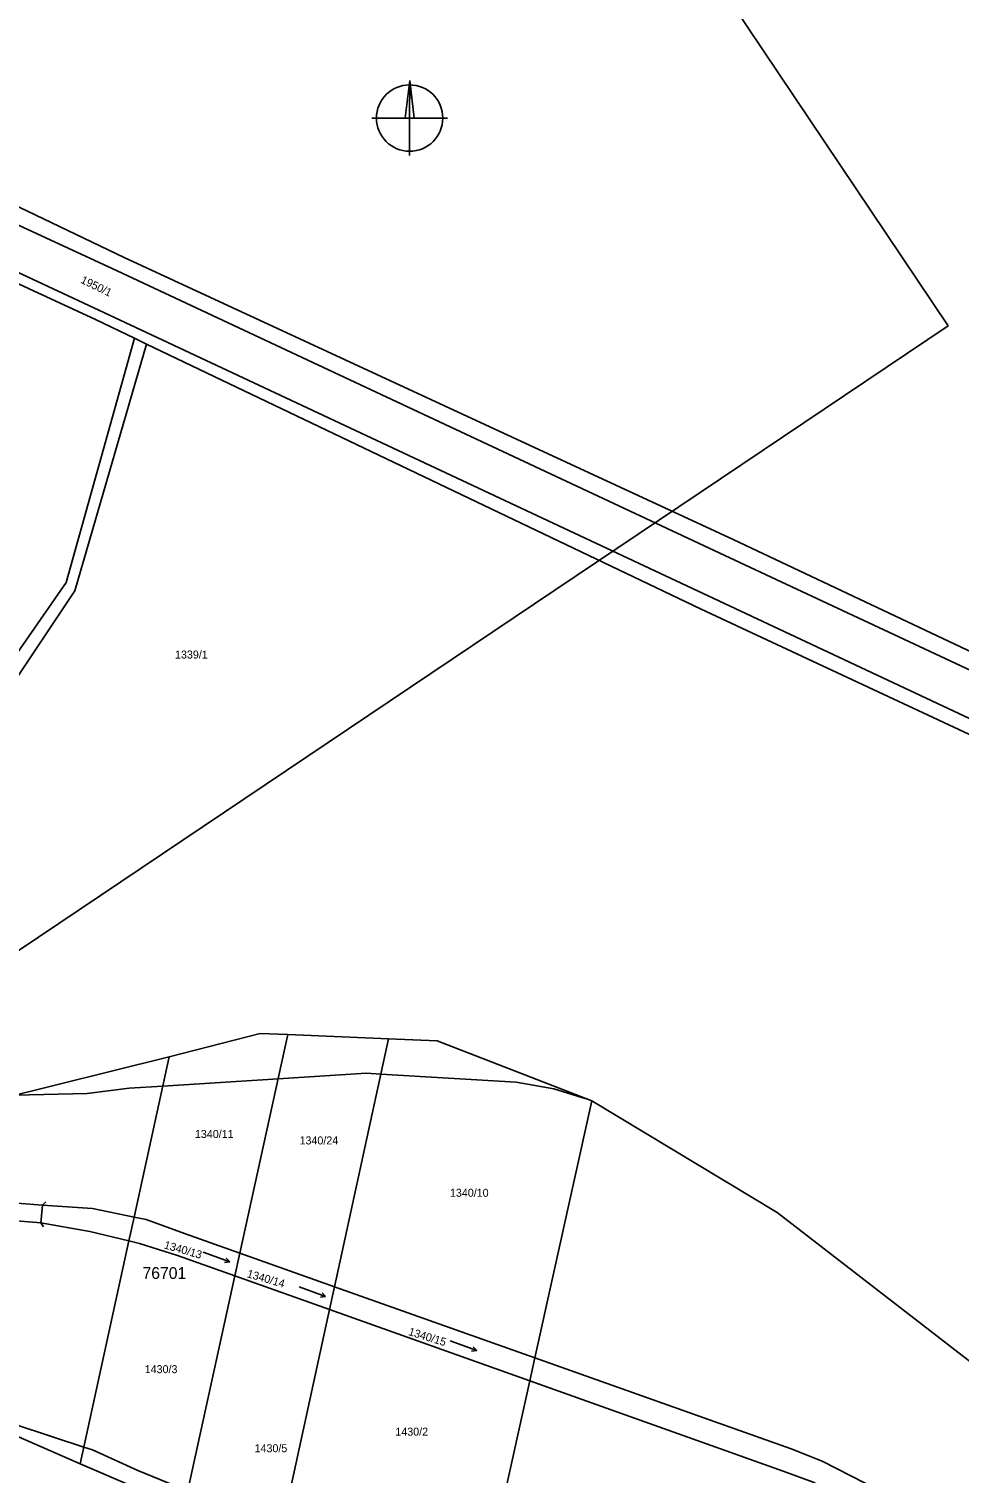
# Model space of a CAD drawing. Extents: x -794765 to -785424, y -1118958 to -1108731.
# Drawn here: x -787203.5 to -787005.8, y -1117691.3 to -1117384.5 of the extents above; entities that cross this region are included whole.
import ezdxf

# ---------------------------------------------------------------- set-up
doc = ezdxf.new("R2010")
doc.units = 0
for name, color, linetype in [('Level 66', 7, 'Continuous'), ('Level 71', 7, 'Continuous'), ('Level 75', 7, 'Continuous'), ('Level 76', 7, 'Continuous'), ('Level 77', 7, 'Continuous'), ('Level 81', 7, 'Continuous')]:
    doc.layers.add(name, color=color, linetype=linetype)

msp = doc.modelspace()

# ---------------------------------------------------------------- linework, layer by layer
at = {"layer": 'Level 66'}
for p, q in [((-787166.44, -1117644.39), (-787160.8, -1117646.44)), ((-787160.8, -1117646.44), (-787161.54, -1117645.64)), ((-787160.8, -1117646.44), (-787161.89, -1117646.58)), ((-787146.08, -1117651.74), (-787140.44, -1117653.79)), ((-787140.44, -1117653.79), (-787141.53, -1117653.93)), ((-787140.44, -1117653.79), (-787141.18, -1117652.99)), ((-787113.97, -1117663.23), (-787108.33, -1117665.28)), ((-787108.33, -1117665.28), (-787109.07, -1117664.48)), ((-787108.33, -1117665.28), (-787109.42, -1117665.42))]:
    msp.add_line(p, q, dxfattribs=at)
at = {"layer": 'Level 71'}
for p, q in [((-787122.56, -1117395.5), (-787123.56, -1117403.43)), ((-787130.64, -1117403.46), (-787114.51, -1117403.5)), ((-787122.59, -1117403.46), (-787122.62, -1117411.43)), ((-787257.85, -1117615.31), (-787008.17, -1117447.61))]:
    msp.add_line(p, q, dxfattribs=at)
msp.add_lwpolyline([(-787008.17, -1117447.61), (-787479.8, -1116745.45), (-787729.47, -1116913.15), (-787257.85, -1117615.31)], dxfattribs=at)
msp.add_lwpolyline([(-787122.56, -1117395.5), (-787121.59, -1117403.46), (-787122.59, -1117403.46)], close=True, dxfattribs=at)
msp.add_circle((-787122.59, -1117403.46), 7.05, dxfattribs=at)
at = {"layer": 'Level 75'}
for p, q in [((-787181.08, -1117450.22), (-787178.49, -1117451.46)), ((-787158.66, -1117644.58), (-787148.45, -1117598.16)), ((-787148.45, -1117598.16), (-787127.04, -1117599.06)), ((-787127.04, -1117599.06), (-787138.55, -1117651.72)), ((-787173.69, -1117602.87), (-787181.14, -1117636.92)), ((-787095.98, -1117666.83), (-787083.89, -1117612.23)), ((-787181.14, -1117636.92), (-787182.24, -1117641.97)), ((-787182.24, -1117641.97), (-787192.6, -1117689.33)), ((-787159.72, -1117649.37), (-787158.66, -1117644.58)), ((-787138.55, -1117651.72), (-787158.66, -1117644.58)), ((-787170.58, -1117698.74), (-787159.72, -1117649.37)), ((-787159.72, -1117649.37), (-787139.61, -1117656.54)), ((-787139.61, -1117656.54), (-787138.55, -1117651.72)), ((-787095.98, -1117666.83), (-787138.55, -1117651.72)), ((-787139.61, -1117656.54), (-787150.69, -1117707.23)), ((-787139.61, -1117656.54), (-787097.06, -1117671.7)), ((-787095.98, -1117666.83), (-787097.06, -1117671.7)), ((-787103.7, -1117701.74), (-787097.06, -1117671.7)), ((-787170.58, -1117698.74), (-787192.6, -1117689.33))]:
    msp.add_line(p, q, dxfattribs=at)
for points in [[(-786706.11, -1117656.27), (-786875.36, -1117577.21), (-787053.8, -1117493.01), (-787183.24, -1117433.1), (-787248.32, -1117401.92)], [(-787181.08, -1117450.22), (-787189.33, -1117446.27), (-787252.97, -1117416.89)], [(-787270.37, -1117609.83), (-787195.54, -1117502.09), (-787181.08, -1117450.22)], [(-787265.2, -1117611.01), (-787193.72, -1117503.85), (-787178.49, -1117451.46)], [(-787178.49, -1117451.46), (-787060.65, -1117507.79), (-786888.93, -1117587.94), (-786715.31, -1117668.78), (-786654.85, -1117697.18), (-786554.23, -1117744.76)], [(-787148.45, -1117598.16), (-787154.33, -1117597.92), (-787173.69, -1117602.87)], [(-787083.89, -1117612.23), (-787116.72, -1117599.48), (-787127.04, -1117599.06)], [(-787265.2, -1117611.01), (-787210.23, -1117611.92), (-787173.69, -1117602.87)], [(-787083.89, -1117612.23), (-787044.5, -1117635.94), (-786988.98, -1117678.85), (-786894.96, -1117721.22), (-786804.51, -1117760.36), (-786783.82, -1117759.58), (-786698.19, -1117799.48), (-786641.23, -1117819.18), (-786564.05, -1117798.26)], [(-787181.14, -1117636.92), (-787190.01, -1117635.11), (-787200.57, -1117634.38), (-787211.61, -1117633.55), (-787292.23, -1117625.71), (-787296.84, -1117625.58)], [(-787296.23, -1117630.19), (-787293.12, -1117630.97), (-787212.29, -1117637.24), (-787200.96, -1117638.15), (-787190.55, -1117639.98), (-787182.24, -1117641.97)], [(-787158.66, -1117644.58), (-787170.42, -1117640.41), (-787178.57, -1117637.44), (-787181.14, -1117636.92)], [(-787182.24, -1117641.97), (-787180.01, -1117642.5), (-787171.88, -1117645.04), (-787159.72, -1117649.37)], [(-787192.6, -1117689.33), (-787260.59, -1117659.56), (-787270.16, -1117662.49), (-787292.35, -1117650.03)], [(-786847.1, -1117813.31), (-786936.77, -1117752.44), (-787017.15, -1117698.96), (-787025.67, -1117693.51), (-787034.95, -1117688.76), (-787041.51, -1117686.17), (-787095.98, -1117666.83)], [(-787097.06, -1117671.7), (-787043.19, -1117690.9), (-787036.8, -1117693.22), (-787027.75, -1117697.82), (-787019.6, -1117702.92), (-786939.62, -1117757.05), (-786798.58, -1117851.66)]]:
    msp.add_lwpolyline(points, dxfattribs=at)
at = {"layer": 'Level 77'}
for p, q in [((-787250.51, -1117405.41), (-787184.71, -1117435.94)), ((-787188.65, -1117444.27), (-787252.33, -1117414.61)), ((-787184.71, -1117435.94), (-787055.59, -1117496.38)), ((-787059.18, -1117504.94), (-787188.65, -1117444.27)), ((-787055.59, -1117496.38), (-786877.84, -1117579.46)), ((-786886.62, -1117585.85), (-787059.18, -1117504.94)), ((-787199.88, -1117633.66), (-787200.57, -1117634.38)), ((-787200.57, -1117634.38), (-787200.96, -1117638.15)), ((-787200.37, -1117638.96), (-787200.96, -1117638.15))]:
    msp.add_line(p, q, dxfattribs=at)
at = {"layer": 'Level 81'}
for points in [[(-787417.72, -1117587.42), (-787400.54, -1117597.07), (-787369.92, -1117613.34), (-787338, -1117627.53), (-787311.28, -1117640.41), (-787297.7, -1117646.95), (-787294.75, -1117647.86), (-787292.59, -1117648.82), (-787265.76, -1117660.71), (-787265.1, -1117660.94), (-787233.78, -1117671.93), (-787227.93, -1117673.86), (-787191.82, -1117685.76), (-787190, -1117686.35), (-787180.34, -1117690.78), (-787169.78, -1117695.08)], [(-787085.07, -1117611.77), (-787091.96, -1117609.68), (-787099.98, -1117608.25), (-787128.67, -1117606.52), (-787131.72, -1117606.34), (-787150.51, -1117607.53), (-787175.05, -1117609.09), (-787182.19, -1117609.54), (-787191.1, -1117610.63), (-787206.5, -1117611)]]:
    msp.add_lwpolyline(points, dxfattribs=at)

# ---------------------------------------------------------------- texts
at = {"layer": 'Level 76'}
for s, rotation, p in [('1950/1', 334, (-787192.64, -1117438.39)), ('1340/13', 344, (-787174.91, -1117643.54)), ('1340/14', 344, (-787157.29, -1117649.66)), ('1340/15', 343, (-787122.98, -1117661.95))]:
    msp.add_text(s, height=1.7, rotation=rotation, dxfattribs=at).set_placement(p)
for s, p in [('1339/1', (-787172.44, -1117518.27)), ('1340/11', (-787168.21, -1117620.11)), ('1340/24', (-787145.98, -1117621.48)), ('1340/10', (-787114.02, -1117632.6)), ('1430/3', (-787178.88, -1117670.07)), ('1430/2', (-787125.62, -1117683.35)), ('1430/5', (-787155.53, -1117686.87))]:
    msp.add_text(s, height=1.7, dxfattribs=at).set_placement(p)
at = {"layer": 'Level 81'}
msp.add_text('76701', height=2.5, dxfattribs=at).set_placement((-787179.35, -1117650.05))

doc.saveas('drawing.dxf')
